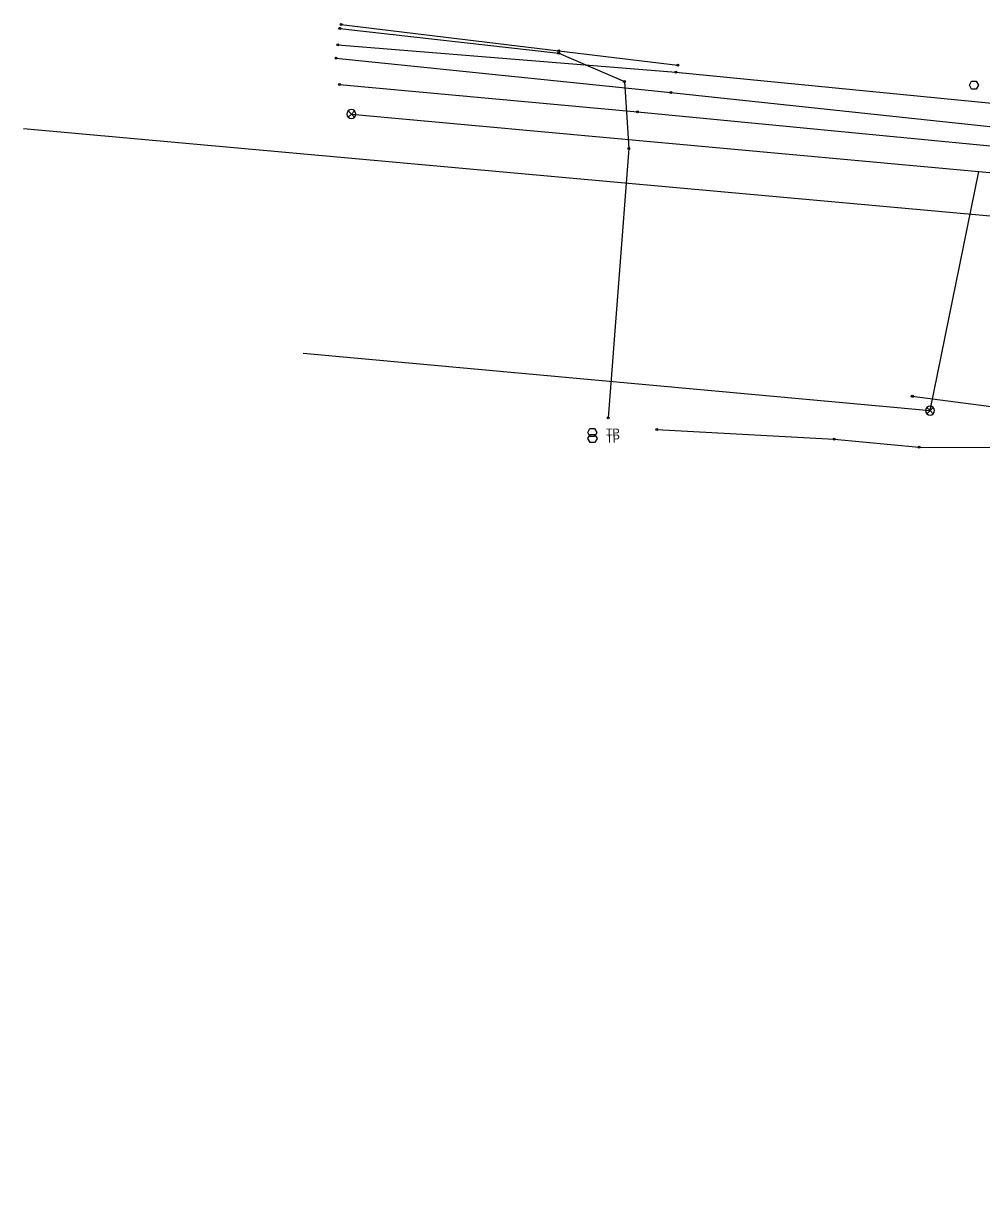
# Model space of a CAD drawing. Extents: x 20500343 to 20505311, y 7953484 to 7954193.
# Drawn here: x 20500343.3 to 20500534.8, y 7953817.6 to 7954051.8 of the extents above; entities that cross this region are included whole.
import ezdxf

# ---------------------------------------------------------------- set-up
doc = ezdxf.new("R2010")
doc.units = 0
for name, color, linetype in [('C-PROP-LINE-LOT', 7, 'Continuous'), ('V-ANNO-NOTE', 7, 'Continuous'), ('V-MON-FND', 7, 'Continuous'), ('V-SSWR-STRC', 7, 'Continuous')]:
    doc.layers.add(name, color=color, linetype=linetype)

msp = doc.modelspace()

# ---------------------------------------------------------------- linework, layer by layer
at = {"layer": 'C-PROP-LINE-LOT'}
for points in [[(20500406.53, 7954050.81), (20500450.29, 7954045.84), (20500463.41, 7954040.18), (20500464.31, 7954026.82), (20500460.16, 7953972.97)], [(20500406.8, 7954051.59), (20500450.33, 7954046.33), (20500474.08, 7954043.43)], [(20500406.13, 7954047.52), (20500473.69, 7954042.07), (20500666.63, 7954023.16), (20500691.11, 7954020.37), (20500735.76, 7954016.9), (20500774.72, 7954014.43), (20500808.62, 7954016.33)], [(20500405.79, 7954044.85), (20500472.72, 7954037.98), (20500549.61, 7954029.82), (20500666.39, 7954020.52), (20500705.15, 7954014.85), (20500746.99, 7954011.28), (20500758.66, 7954009.18), (20500758.57, 7954000.24), (20500758.16, 7953954.61), (20500759.69, 7953925.46)], [(20500406.47, 7954039.57), (20500466.05, 7954034.11), (20500535.84, 7954027.4), (20500662.16, 7954017.11), (20500704.07, 7954013.07), (20500745.63, 7954009.37), (20500792.32, 7954005.22), (20500811.87, 7954003.45), (20500860.59, 7953999.05), (20500920.01, 7953993.63), (20500957.01, 7953989.31), (20500990.1, 7953987.34), (20501028.58, 7953985.6), (20501071.83, 7953984.74), (20501141.27, 7953979.76), (20501204.8, 7953974.46), (20501273.24, 7953968.85)], [(20500408.85, 7954033.69), (20500534.28, 7954022.2), (20500733.06, 7954003.91), (20500967.33, 7953980.02)], [(20500343.29, 7954030.83), (20500591.11, 7954008.44), (20500942.44, 7953977.04), (20500960.49, 7953579.51)], [(20500399.23, 7953985.89), (20500524.52, 7953974.42), (20500534.28, 7954022.2)], [(20500520.98, 7953977.28), (20500560.2, 7953972.18), (20500580.11, 7953968.09), (20500618.43, 7953964.47), (20500633.81, 7953963.45), (20500668.21, 7953960.34), (20500693.49, 7953957.8), (20500747.72, 7953955.96), (20500802.14, 7953953.65), (20500876.21, 7953950.48), (20500928.48, 7953945.92), (20500984.31, 7953941.41), (20501068.76, 7953929.07), (20501169.59, 7953917.28), (20501247.95, 7953910.8), (20501285.38, 7953908.94), (20501306.14, 7953908.1), (20501320.57, 7953910.34), (20501331.41, 7953911.48)], [(20500469.9, 7953970.65), (20500505.35, 7953968.7), (20500522.37, 7953967.11), (20500565.63, 7953966.99), (20500619.43, 7953961.41), (20500633.65, 7953961.99), (20500668.11, 7953958.55), (20500688.24, 7953956.38), (20500722.3, 7953952.32), (20500751.12, 7953948.12), (20500793.42, 7953946.39), (20500829.09, 7953943.31), (20500867.84, 7953939.12), (20500927.83, 7953934.54), (20500971.05, 7953923.41), (20500978.23, 7953919.45), (20500994.58, 7953914.36)]]:
    msp.add_lwpolyline(points, dxfattribs=at)
at = {"layer": 'V-ANNO-NOTE'}
for centre in [(20500406.53, 7954050.81), (20500406.8, 7954051.59), (20500406.13, 7954047.52), (20500405.79, 7954044.85), (20500450.29, 7954045.84), (20500450.33, 7954046.33), (20500474.08, 7954043.43), (20500463.41, 7954040.18), (20500473.69, 7954042.07), (20500406.47, 7954039.57), (20500472.72, 7954037.98), (20500466.05, 7954034.11), (20500464.31, 7954026.82), (20500520.98, 7953977.28), (20500460.16, 7953972.97), (20500469.9, 7953970.65), (20500505.35, 7953968.7), (20500522.37, 7953967.11)]:
    msp.add_circle(centre, 0.2, dxfattribs=at)
at = {"layer": 'V-MON-FND'}
for points in [[(20500532.38, 7954039.45), (20500532.83, 7954040.24), (20500533.75, 7954040.24), (20500534.2, 7954039.45), (20500533.75, 7954038.66), (20500532.83, 7954038.66), (20500532.38, 7954039.45)], [(20500456.09, 7953970.03), (20500456.54, 7953970.82), (20500457.46, 7953970.82), (20500457.91, 7953970.03), (20500457.46, 7953969.24), (20500456.54, 7953969.24), (20500456.09, 7953970.03)], [(20500456.13, 7953968.83), (20500456.58, 7953969.63), (20500457.5, 7953969.63), (20500457.95, 7953968.83), (20500457.5, 7953968.04), (20500456.58, 7953968.04), (20500456.13, 7953968.83)]]:
    msp.add_lwpolyline(points, dxfattribs=at)
at = {"layer": 'V-SSWR-STRC'}
for points in [[(20500408.21, 7954033.06), (20500408.85, 7954033.69), (20500408.21, 7954034.33)], [(20500409.49, 7954034.33), (20500408.85, 7954033.69), (20500409.49, 7954033.06)], [(20500343.29, 7954030.83), (20500343.29, 7954030.83), (20500343.29, 7954030.83)], [(20500343.29, 7954030.83), (20500343.29, 7954030.83), (20500343.29, 7954030.83)], [(20500534.28, 7954022.2), (20500534.28, 7954022.2), (20500534.28, 7954022.2)], [(20500534.28, 7954022.2), (20500534.28, 7954022.2), (20500534.28, 7954022.2)], [(20500399.23, 7953985.89), (20500399.23, 7953985.89), (20500399.23, 7953985.89)], [(20500399.23, 7953985.89), (20500399.23, 7953985.89), (20500399.23, 7953985.89)], [(20500523.88, 7953973.79), (20500524.52, 7953974.42), (20500523.88, 7953975.06)], [(20500525.16, 7953975.06), (20500524.52, 7953974.42), (20500525.16, 7953973.79)]]:
    msp.add_lwpolyline(points, dxfattribs=at)
for centre, radius, start, end in [((20500408.85, 7954033.69), 0.899, 135, 225), ((20500408.85, 7954033.69), 0.899, 45, 135), ((20500408.85, 7954033.69), 0.899, 315, 45), ((20500343.29, 7954030.83), 0.0015, 225, 315), ((20500343.29, 7954030.83), 0.0015, 45, 135), ((20500343.29, 7954030.83), 0.0015, 135, 225), ((20500343.29, 7954030.83), 0.0015, 315, 45), ((20500408.85, 7954033.69), 0.899, 225, 315), ((20500534.28, 7954022.2), 0.0015, 225, 315), ((20500534.28, 7954022.2), 0.0015, 45, 135), ((20500534.28, 7954022.2), 0.0015, 135, 225), ((20500534.28, 7954022.2), 0.0015, 315, 45), ((20500399.23, 7953985.89), 0.0015, 225, 315), ((20500399.23, 7953985.89), 0.0015, 45, 135), ((20500399.23, 7953985.89), 0.0015, 135, 225), ((20500399.23, 7953985.89), 0.0015, 315, 45), ((20500524.52, 7953974.42), 0.899, 135, 225), ((20500524.52, 7953974.42), 0.899, 45, 135), ((20500524.52, 7953974.42), 0.899, 315, 45), ((20500524.52, 7953974.42), 0.899, 225, 315)]:
    msp.add_arc(centre, radius, start, end, dxfattribs=at)

# ---------------------------------------------------------------- texts
at = {"layer": 'V-MON-FND'}
for p in [(20500459.74, 7953969.23), (20500459.78, 7953968.04)]:
    msp.add_text('TP', height=1.599, dxfattribs=at).set_placement(p)

doc.saveas('drawing.dxf')
